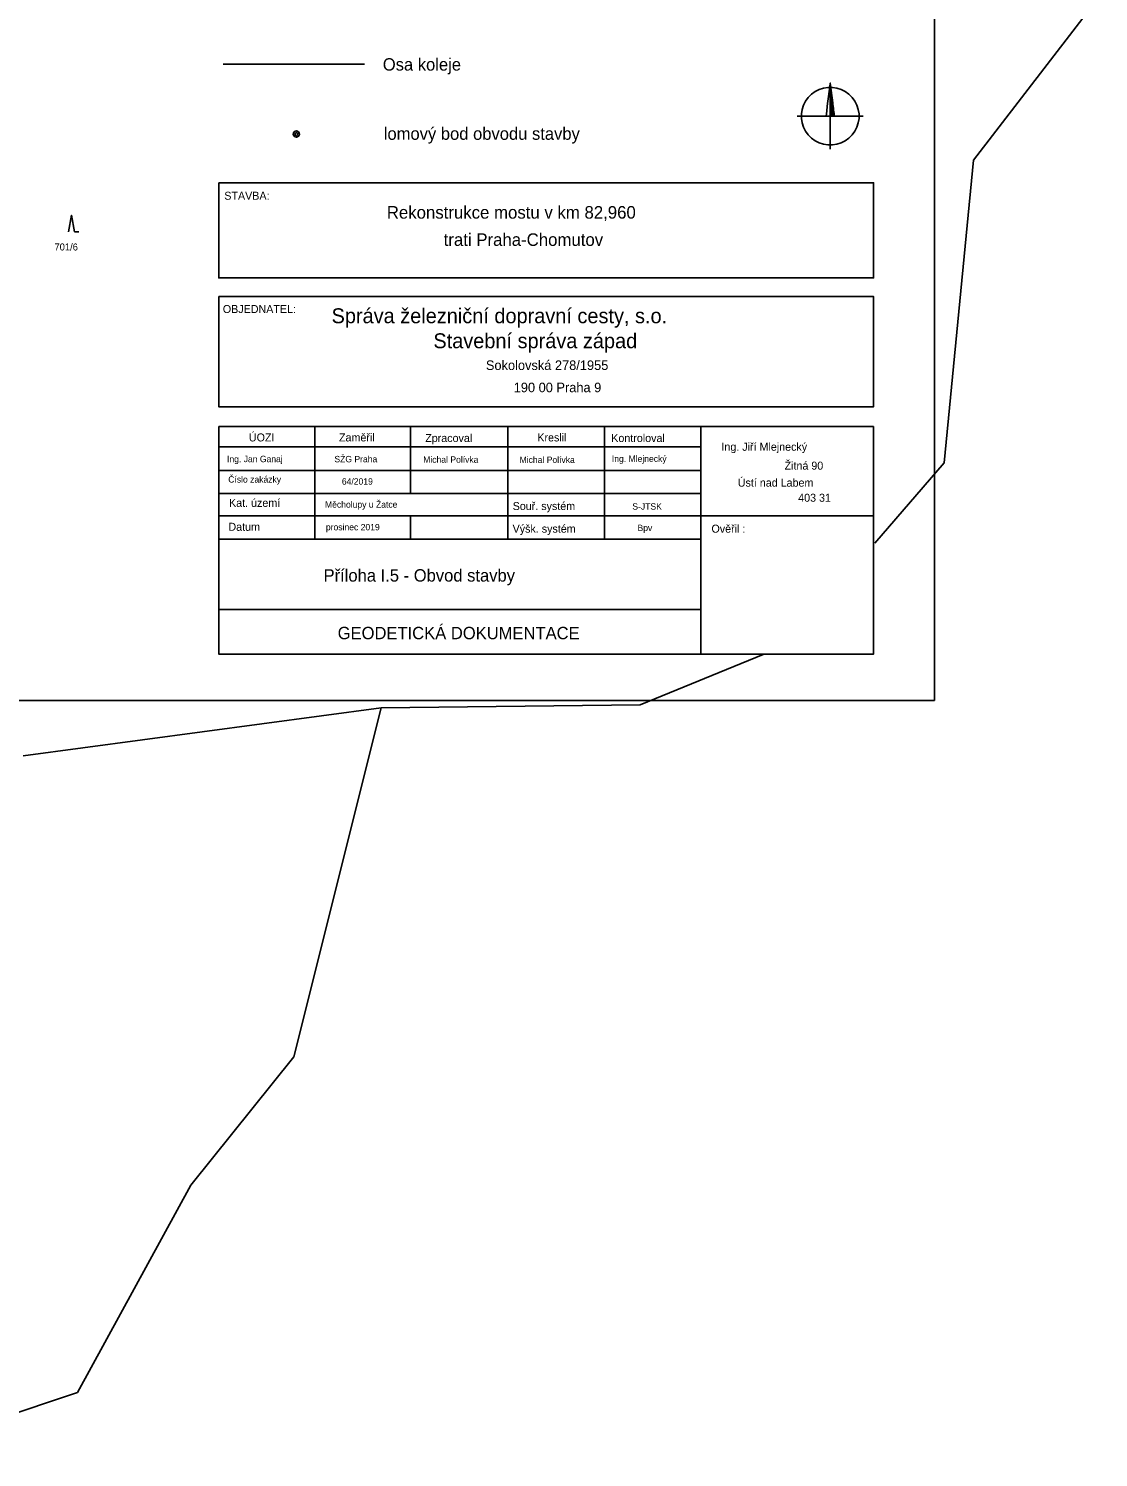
# Model space of a CAD drawing. Extents: x -801907 to -800293, y -1016964 to -1015684.
# Drawn here: x -800931.6 to -800672.4, y -1016927 to -1016580.7 of the extents above; entities that cross this region are included whole.
import ezdxf

# ---------------------------------------------------------------- set-up
doc = ezdxf.new("R2010")
doc.units = 0
for name, color, linetype in [('body', 7, 'Continuous'), ('Default', 7, 'Continuous'), ('KN_HRANICE', 7, 'Continuous'), ('KN_KULTURY', 7, 'Continuous'), ('KN_PARCELY', 7, 'Continuous'), ('LEGENDA', 7, 'Continuous'), ('tabulka', 7, 'Continuous')]:
    doc.layers.add(name, color=color, linetype=linetype)

# ---------------------------------------------------------------- blocks, each defined once
blk = doc.blocks.new('308')
at = {"layer": 'Default'}
blk.add_lwpolyline([(-0.75, 0), (0, 4), (0.75, 0), (1.75, 0)], dxfattribs=at)
blk = doc.blocks.new('SEVER')
at = {"layer": 'Default'}
for points in [[(5.5, 69.8), (16.3, 68.1), (26.7, 64.7), (36.5, 59.7), (45.4, 53.2), (53.2, 45.4), (59.7, 36.5), (64.7, 26.7), (68.1, 16.3), (69.8, 5.5), (69.8, -5.5), (68.1, -16.3), (64.7, -26.7), (59.7, -36.5), (53.2, -45.4), (45.4, -53.2), (36.5, -59.7), (26.7, -64.7), (16.3, -68.1), (5.5, -69.8), (-5.5, -69.8), (-16.3, -68.1), (-26.7, -64.7), (-36.5, -59.7), (-45.4, -53.2), (-53.2, -45.4), (-59.7, -36.5), (-64.7, -26.7), (-68.1, -16.3), (-69.8, -5.5), (-69.8, 5.5), (-68.1, 16.3), (-64.7, 26.7), (-59.7, 36.5), (-53.2, 45.4), (-45.4, 53.2), (-36.5, 59.7), (-26.7, 64.7), (-16.3, 68.1), (-5.5, 69.8), (5.5, 69.8)], [(-10, 0), (-8.5, 12), (-7, 24), (-5.5, 36), (-4, 48), (-2.5, 60), (-1, 72), (0, 80), (1.5, 68), (3, 56), (4.5, 44), (6, 32), (7.5, 20), (9, 8), (10, 0), (9.2, 0.8), (9.2, 5.6), (8.4, 12), (8.4, 0.8), (7.6, 0.8), (7.6, 13.5), (7.6, 18.4), (6.8, 24.8), (6.8, 12.1), (6.8, 0.8), (6, 0.8), (6, 13.5), (6, 26.2), (6, 31.2), (5.2, 36.8), (5.2, 24.1), (5.2, 11.4), (5.2, 0.8), (4.4, 0.8), (4.4, 13.5), (4.4, 26.2), (4.4, 38.9), (4.4, 43.2), (3.6, 50.4), (3.6, 37.7), (3.6, 25), (3.6, 12.3), (3.6, 0.8), (2.8, 0.8), (2.8, 13.5), (2.8, 26.2), (2.8, 38.9), (2.8, 51.6), (2.8, 56), (2, 63.2), (2, 50.5), (2, 37.8), (2, 25.1), (2, 12.4), (2, 0.8), (1.2, 0.8), (1.2, 13.5), (1.2, 26.2), (1.2, 38.9), (1.2, 51.6), (1.2, 64.3), (1.2, 69.6), (0.4, 76), (0.4, 63.3), (0.4, 50.6), (0.4, 37.9), (0.4, 25.2), (0.4, 12.5), (0.4, 0.8)], [(0, 80), (0, 67.3), (0, 54.6), (0, 41.9), (0, 29.2), (0, 16.5), (0, 3.8), (0, -8.9), (0, -21.6), (0, -34.3), (0, -47), (0, -59.7), (0, -72.4), (0, -80)], [(80, 0), (67.3, 0), (54.6, 0), (41.9, 0), (29.2, 0), (16.5, 0), (3.8, 0), (-8.9, 0), (-21.6, 0), (-34.3, 0), (-47, 0), (-59.7, 0), (-72.4, 0), (-80, 0)]]:
    blk.add_lwpolyline(points, dxfattribs=at)

msp = doc.modelspace()

# ---------------------------------------------------------------- linework, layer by layer
at = {"layer": 'body'}
for radius in [0.75, 0.35]:
    msp.add_circle((-800866.7, -1016606.28), radius, dxfattribs=at)
at = {"layer": 'KN_HRANICE'}
for p, q in [((-800672.38, -1016573.21), (-800702.65, -1016612.58)), ((-800702.65, -1016612.58), (-800709.73, -1016685.98)), ((-800709.73, -1016685.98), (-800726.57, -1016705.41)), ((-800753.62, -1016732.42), (-800783.37, -1016744.64)), ((-800932.89, -1016756.98), (-800846.15, -1016745.38)), ((-800846.15, -1016745.38), (-800867.3, -1016829.9)), ((-800783.37, -1016744.64), (-800846.15, -1016745.38)), ((-800867.3, -1016829.9), (-800892.3, -1016861.04)), ((-800892.3, -1016861.04), (-800919.72, -1016911.28)), ((-800966.67, -1016927.02), (-800919.72, -1016911.28))]:
    msp.add_line(p, q, dxfattribs=at)
at = {"layer": 'LEGENDA'}
msp.add_line((-800884.41, -1016589.31), (-800850.21, -1016589.31), dxfattribs=at)
msp.add_lwpolyline([(-801306.12, -1016323.56), (-800712.12, -1016323.56), (-800712.12, -1016743.56), (-801306.12, -1016743.56)], close=True, dxfattribs=at)
at = {"layer": 'tabulka'}
for p, q in [((-800885.51, -1016677.17), (-800726.85, -1016677.17)), ((-800862.22, -1016677.17), (-800862.22, -1016704.49)), ((-800839.07, -1016677.17), (-800839.07, -1016693.37)), ((-800815.47, -1016677.17), (-800815.47, -1016704.49)), ((-800792.02, -1016677.17), (-800792.02, -1016704.49)), ((-800768.72, -1016732.3), (-800768.72, -1016677.17)), ((-800885.51, -1016682.08), (-800768.72, -1016682.08)), ((-800885.51, -1016687.79), (-800768.72, -1016687.79)), ((-800885.51, -1016693.37), (-800768.72, -1016693.37)), ((-800885.51, -1016698.79), (-800726.85, -1016698.79)), ((-800839.07, -1016698.79), (-800839.07, -1016704.49)), ((-800885.51, -1016704.49), (-800768.72, -1016704.49)), ((-800885.51, -1016721.48), (-800768.72, -1016721.48))]:
    msp.add_line(p, q, dxfattribs=at)
for points in [[(-800885.51, -1016618.08), (-800726.85, -1016618.08), (-800726.85, -1016641.15), (-800885.51, -1016641.15)], [(-800885.51, -1016645.67), (-800726.85, -1016645.67), (-800726.85, -1016672.36), (-800885.51, -1016672.36)]]:
    msp.add_lwpolyline(points, close=True, dxfattribs=at)
msp.add_lwpolyline([(-800726.85, -1016677.17), (-800726.85, -1016732.3), (-800885.51, -1016732.3), (-800885.51, -1016677.17)], dxfattribs=at)

# ---------------------------------------------------------------- block references
at = {"layer": 'KN_KULTURY'}
msp.add_blockref('308', (-800921.18, -1016629.94), dxfattribs=at)
at = {"layer": 'LEGENDA', "xscale": 0.1, "yscale": 0.10000000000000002}
msp.add_blockref('SEVER', (-800737.36, -1016601.93), dxfattribs=at)

# ---------------------------------------------------------------- texts
at = {"layer": 'KN_PARCELY'}
msp.add_text('701/6', height=1.7, dxfattribs=at).set_placement((-800925.31, -1016634.49))
at = {"layer": 'LEGENDA'}
for s, p in [('Osa koleje', (-800845.76, -1016590.89)), ('lomový bod obvodu stavby', (-800845.52, -1016607.67))]:
    msp.add_text(s, height=3, dxfattribs=at).set_placement(p)
at = {"layer": 'tabulka'}
for s, height, p in [('STAVBA:', 1.94, (-800884.16, -1016622.19)), ('Rekonstrukce mostu v km 82,960', 3.04, (-800844.79, -1016626.77)), ('trati Praha-Chomutov', 3.04, (-800831.01, -1016633.38)), ('OBJEDNATEL:', 1.94, (-800884.52, -1016649.65)), ('Správa železniční dopravní cesty, s.o.', 3.61, (-800858.17, -1016652.12)), ('Stavební správa západ', 3.61, (-800833.5, -1016658.18)), ('Sokolovská 278/1955', 2.32, (-800820.78, -1016663.46)), ('190 00 Praha 9', 2.32, (-800814.04, -1016668.85)), ('ÚOZI', 1.94, (-800878.2, -1016680.77)), ('Zaměřil', 1.94, (-800856.37, -1016680.77)), ('Zpracoval', 1.94, (-800835.48, -1016680.92)), ('Kreslil', 1.94, (-800808.32, -1016680.77)), ('Kontroloval', 1.94, (-800790.41, -1016680.92)), ('Ing. Jiří Mlejnecký', 1.94, (-800763.71, -1016683.03)), ('Ing. Jan Ganaj', 1.552, (-800883.5, -1016685.8)), ('SŽG Praha', 1.552, (-800857.48, -1016685.83)), ('Michal Polívka', 1.552, (-800835.96, -1016685.95)), ('Michal Polívka', 1.552, (-800812.62, -1016685.99)), ('Ing. Mlejnecký', 1.552, (-800790.26, -1016685.73)), ('Žitná 90', 1.94, (-800748.42, -1016687.61)), ('Číslo zakázky', 1.552, (-800883.2, -1016690.75)), ('64/2019', 1.552, (-800855.67, -1016691.24)), ('Ústí nad Labem', 1.94, (-800759.75, -1016691.73)), ('403 31', 1.94, (-800745.12, -1016695.39)), ('Kat. území', 1.94, (-800883.01, -1016696.63)), ('Měcholupy u Žatce', 1.552, (-800859.75, -1016696.83)), ('Souř. systém', 1.94, (-800814.29, -1016697.4)), ('S-JTSK', 1.552, (-800785.3, -1016697.31)), ('Datum', 1.94, (-800883.16, -1016702.43)), ('prosinec 2019', 1.552, (-800859.54, -1016702.32)), ('Výšk. systém', 1.94, (-800814.31, -1016702.89)), ('Bpv', 1.552, (-800784.04, -1016702.5)), ('Ověřil :', 1.94, (-800766.13, -1016702.89)), ('Příloha I.5 - Obvod stavby', 3, (-800860.11, -1016714.74)), ('GEODETICKÁ DOKUMENTACE ', 3, (-800856.69, -1016728.71))]:
    msp.add_text(s, height=height, dxfattribs=at).set_placement(p)

doc.saveas('drawing.dxf')
